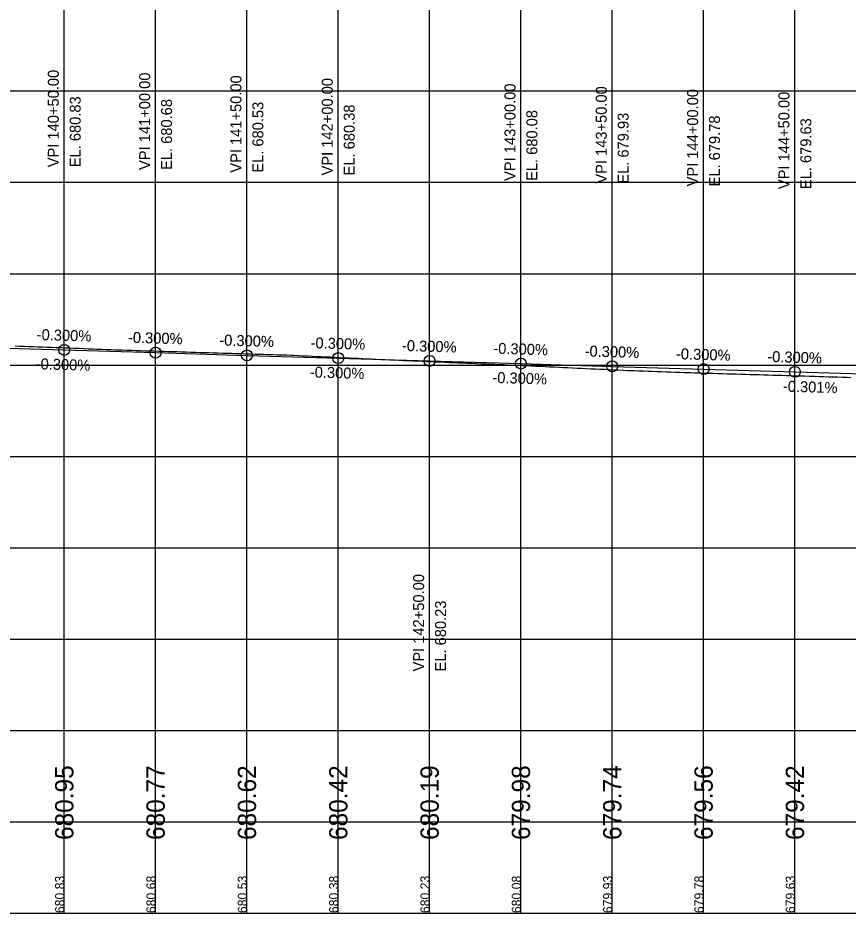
# Model space of a CAD drawing. Extents: x -7164 to 2214450, y -19642 to 253469.
# Drawn here: x 21224.6 to 21679.1, y -3000 to -2510 of the extents above; entities that cross this region are included whole.
import ezdxf

# ---------------------------------------------------------------- set-up
doc = ezdxf.new("R2010")
doc.units = 0
for name, color, linetype in [('DESIGN - PROFILE - Proposed', 7, 'Continuous'), ('DESIGN - PROFILE - Proposed Curve Text', 7, 'Continuous'), ('DESIGN - PROFILE - Proposed Text', 7, 'Continuous'), ('DESIGN - SCRATCH - User 1', 7, 'Continuous'), ('DESIGN - SHEET - Light Grid', 7, 'Continuous'), ('SURVEY - PROFILE - Ground Line with Text', 7, 'Continuous')]:
    doc.layers.add(name, color=color, linetype=linetype)

msp = doc.modelspace()

# ---------------------------------------------------------------- linework, layer by layer
at = {"layer": 'DESIGN - PROFILE - Proposed'}
msp.add_lwpolyline([(21200, -2690.23), (21250, -2691.73), (21300, -2693.23), (21350, -2694.73), (21400, -2696.23), (21450, -2697.73), (21500, -2699.23), (21550, -2700.73), (21600, -2702.23), (21650, -2703.73), (21700, -2705.23)], dxfattribs=at)
msp.add_lwpolyline([(21200, -2690.23), (21250, -2691.73), (21300, -2693.23), (21350, -2694.73), (21400, -2696.23), (21450, -2697.73), (21500, -2699.23), (21550, -2700.73), (21600, -2702.23), (21650, -2703.73), (21700, -2705.23)], dxfattribs=at)
at = {"layer": 'DESIGN - PROFILE - Proposed Text'}
for centre in [(21250, -2691.73), (21250, -2691.73), (21300, -2693.23), (21300, -2693.23), (21350, -2694.73), (21350, -2694.73), (21400, -2696.23), (21400, -2696.23), (21450, -2697.73), (21450, -2697.73), (21500, -2699.23), (21500, -2699.23), (21550, -2700.73), (21550, -2700.73), (21600, -2702.23), (21600, -2702.23), (21650, -2703.73), (21650, -2703.73)]:
    msp.add_circle(centre, 3, dxfattribs=at)
at = {"layer": 'DESIGN - SCRATCH - User 1'}
msp.add_line((15000, -3000), (24100, -3000), dxfattribs=at)
msp.add_line((15000, -3000), (24100, -3000), dxfattribs=at)
at = {"layer": 'DESIGN - SHEET - Light Grid'}
for p, q in [((21250, -3000), (21250, -1000)), ((21250, -3000), (21250, -1000)), ((21300, -3000), (21300, -1000)), ((21300, -3000), (21300, -1000)), ((21350, -3000), (21350, -1000)), ((21350, -3000), (21350, -1000)), ((21400, -3000), (21400, -1000)), ((21400, -3000), (21400, -1000)), ((21450, -3000), (21450, -1000)), ((21450, -3000), (21450, -1000)), ((21500, -3000), (21500, -1000)), ((21500, -3000), (21500, -1000)), ((21550, -3000), (21550, -1000)), ((21550, -3000), (21550, -1000)), ((21600, -3000), (21600, -1000)), ((21600, -3000), (21600, -1000)), ((21650, -3000), (21650, -1000)), ((21650, -3000), (21650, -1000)), ((15000, -2550), (24100, -2550)), ((15000, -2550), (24100, -2550)), ((15000, -2600), (24100, -2600)), ((15000, -2600), (24100, -2600)), ((15000, -2650), (24100, -2650)), ((15000, -2650), (24100, -2650)), ((15000, -2700), (24100, -2700)), ((15000, -2700), (24100, -2700)), ((15000, -2750), (24100, -2750)), ((15000, -2750), (24100, -2750)), ((15000, -2800), (24100, -2800)), ((15000, -2800), (24100, -2800)), ((15000, -2850), (24100, -2850)), ((15000, -2850), (24100, -2850)), ((15000, -2900), (24100, -2900)), ((15000, -2900), (24100, -2900)), ((15000, -2950), (24100, -2950)), ((15000, -2950), (24100, -2950)), ((15000, -3000), (24100, -3000)), ((15000, -3000), (24100, -3000))]:
    msp.add_line(p, q, dxfattribs=at)
at = {"layer": 'SURVEY - PROFILE - Ground Line with Text'}
for points in [[(21223.08, -2689.48), (21225.62, -2689.59), (21228.08, -2689.67), (21230.62, -2689.79), (21233.08, -2689.87), (21235.62, -2689.98), (21238.08, -2690.07), (21240.62, -2690.18), (21243.08, -2690.26), (21245.62, -2690.38), (21248.08, -2690.46), (21250.62, -2690.57), (21253.08, -2690.65), (21255.62, -2690.77), (21258.08, -2690.85), (21260.62, -2690.96), (21263.08, -2691.05), (21265.62, -2691.16), (21268.08, -2691.24), (21270.62, -2691.36), (21273.08, -2691.44), (21275.62, -2691.55), (21278.08, -2691.64), (21279.23, -2691.67), (21281.77, -2691.75), (21284.23, -2691.83), (21286.77, -2691.91), (21289.23, -2691.99), (21291.77, -2692.06), (21294.23, -2692.15), (21296.77, -2692.22), (21299.23, -2692.31), (21299.25, -2692.31), (21301.79, -2692.38), (21304.25, -2692.46), (21306.79, -2692.54), (21309.25, -2692.61), (21311.79, -2692.69), (21314.25, -2692.76), (21316.79, -2692.84), (21319.25, -2692.91), (21321.79, -2692.99), (21324.25, -2693.07), (21326.79, -2693.14), (21329.25, -2693.22), (21331.79, -2693.29), (21334.25, -2693.37), (21336.79, -2693.45), (21339.25, -2693.52), (21341.79, -2693.6), (21344.25, -2693.67), (21346.78, -2693.75), (21349.25, -2693.82), (21351.78, -2693.9), (21354.25, -2693.98), (21356.78, -2694.05), (21359.25, -2694.13), (21361.78, -2694.2), (21364.25, -2694.28), (21366.78, -2694.36), (21369.25, -2694.43), (21371.78, -2694.51), (21374.25, -2694.58), (21374.77, -2694.61), (21375.72, -2694.65), (21378.2, -2694.78), (21380.72, -2694.89), (21383.2, -2695.02), (21385.72, -2695.13), (21388.2, -2695.26), (21390.72, -2695.37), (21393.2, -2695.5), (21395.72, -2695.61), (21398.2, -2695.74), (21400.72, -2695.85), (21403.2, -2695.98), (21405.72, -2696.09), (21408.2, -2696.22), (21410.72, -2696.33), (21413.2, -2696.46), (21415.72, -2696.56), (21415.77, -2696.57), (21418.25, -2696.68), (21420.77, -2696.79), (21423.24, -2696.9), (21425.77, -2697.01), (21428.24, -2697.13), (21430.77, -2697.23), (21433.24, -2697.35), (21435.77, -2697.45), (21438.24, -2697.57), (21440.77, -2697.68), (21443.24, -2697.79)], [(21223.08, -2689.48), (21225.62, -2689.59), (21228.08, -2689.67), (21230.62, -2689.79), (21233.08, -2689.87), (21235.62, -2689.98), (21238.08, -2690.07), (21240.62, -2690.18), (21243.08, -2690.26), (21245.62, -2690.38), (21248.08, -2690.46), (21250.62, -2690.57), (21253.08, -2690.65), (21255.62, -2690.77), (21258.08, -2690.85), (21260.62, -2690.96), (21263.08, -2691.05), (21265.62, -2691.16), (21268.08, -2691.24), (21270.62, -2691.36), (21273.08, -2691.44), (21275.62, -2691.55), (21278.08, -2691.64), (21279.23, -2691.67), (21281.77, -2691.75), (21284.23, -2691.83), (21286.77, -2691.91), (21289.23, -2691.99), (21291.77, -2692.06), (21294.23, -2692.15), (21296.77, -2692.22), (21299.23, -2692.31), (21299.25, -2692.31), (21301.79, -2692.38), (21304.25, -2692.46), (21306.79, -2692.54), (21309.25, -2692.61), (21311.79, -2692.69), (21314.25, -2692.76), (21316.79, -2692.84), (21319.25, -2692.91), (21321.79, -2692.99), (21324.25, -2693.07), (21326.79, -2693.14), (21329.25, -2693.22), (21331.79, -2693.29), (21334.25, -2693.37), (21336.79, -2693.45), (21339.25, -2693.52), (21341.79, -2693.6), (21344.25, -2693.67), (21346.78, -2693.75), (21349.25, -2693.82), (21351.78, -2693.9), (21354.25, -2693.98), (21356.78, -2694.05), (21359.25, -2694.13), (21361.78, -2694.2), (21364.25, -2694.28), (21366.78, -2694.36), (21369.25, -2694.43), (21371.78, -2694.51), (21374.25, -2694.58), (21374.77, -2694.61), (21375.72, -2694.65), (21378.2, -2694.78), (21380.72, -2694.89), (21383.2, -2695.02), (21385.72, -2695.13), (21388.2, -2695.26), (21390.72, -2695.37), (21393.2, -2695.5), (21395.72, -2695.61), (21398.2, -2695.74), (21400.72, -2695.85), (21403.2, -2695.98), (21405.72, -2696.09), (21408.2, -2696.22), (21410.72, -2696.33), (21413.2, -2696.46), (21415.72, -2696.56), (21415.77, -2696.57), (21418.25, -2696.68), (21420.77, -2696.79), (21423.24, -2696.9), (21425.77, -2697.01), (21428.24, -2697.13), (21430.77, -2697.23), (21433.24, -2697.35), (21435.77, -2697.45), (21438.24, -2697.57), (21440.77, -2697.68), (21443.24, -2697.79)], [(21443.24, -2697.79), (21445.77, -2697.9), (21448.24, -2698.01), (21450.77, -2698.12), (21453.23, -2698.23), (21455.77, -2698.34), (21458.23, -2698.46), (21460.77, -2698.55), (21463.23, -2698.66), (21465.77, -2698.75), (21468.23, -2698.87), (21470.77, -2698.96), (21473.24, -2699.07), (21475.77, -2699.16), (21478.24, -2699.28), (21480.77, -2699.37), (21483.24, -2699.48), (21485.77, -2699.57), (21488.24, -2699.69), (21490.77, -2699.78), (21493.24, -2699.9), (21495.77, -2699.99), (21496.4, -2700.02), (21498.23, -2700.1), (21500.71, -2700.22), (21503.23, -2700.34), (21505.71, -2700.46), (21508.23, -2700.57), (21510.71, -2700.7), (21513.23, -2700.81), (21515.71, -2700.94), (21518.23, -2701.05), (21520.71, -2701.17), (21523.23, -2701.29), (21525.71, -2701.41), (21528.23, -2701.52), (21530.71, -2701.65), (21533.23, -2701.76), (21535.71, -2701.88), (21538.23, -2702), (21540.71, -2702.12), (21543.23, -2702.23), (21545.71, -2702.36), (21548.23, -2702.47), (21550.71, -2702.6), (21553.23, -2702.71), (21555.71, -2702.83), (21558.23, -2702.95), (21559.45, -2702.98), (21561.92, -2703.05), (21564.45, -2703.16), (21566.92, -2703.23), (21569.45, -2703.35), (21571.92, -2703.42), (21574.45, -2703.53), (21576.92, -2703.6), (21579.45, -2703.71), (21581.92, -2703.78), (21584.45, -2703.9), (21586.92, -2703.97), (21589.45, -2704.08), (21590.43, -2704.11), (21592.9, -2704.18), (21595.43, -2704.25), (21597.9, -2704.32), (21600.43, -2704.4), (21602.9, -2704.47), (21605.43, -2704.54), (21607.9, -2704.61), (21610.43, -2704.69), (21612.9, -2704.76), (21615.43, -2704.83), (21617.91, -2704.9), (21620.43, -2704.98), (21622.91, -2705.05), (21625.43, -2705.12), (21627.91, -2705.19), (21630.43, -2705.26), (21632.91, -2705.33), (21635.43, -2705.41), (21637.91, -2705.48), (21640.43, -2705.55), (21642.91, -2705.62), (21645.43, -2705.7), (21647.91, -2705.77), (21650.43, -2705.84), (21652.91, -2705.91), (21655.42, -2705.99), (21657.91, -2706.06), (21660.42, -2706.13), (21660.89, -2706.14), (21663.38, -2706.23), (21665.89, -2706.3), (21668.38, -2706.38), (21670.89, -2706.46), (21673.38, -2706.54), (21675.89, -2706.61), (21678.38, -2706.7), (21680.89, -2706.77)], [(21443.24, -2697.79), (21445.77, -2697.9), (21448.24, -2698.01), (21450.77, -2698.12), (21453.23, -2698.23), (21455.77, -2698.34), (21458.23, -2698.46), (21460.77, -2698.55), (21463.23, -2698.66), (21465.77, -2698.75), (21468.23, -2698.87), (21470.77, -2698.96), (21473.24, -2699.07), (21475.77, -2699.16), (21478.24, -2699.28), (21480.77, -2699.37), (21483.24, -2699.48), (21485.77, -2699.57), (21488.24, -2699.69), (21490.77, -2699.78), (21493.24, -2699.9), (21495.77, -2699.99), (21496.4, -2700.02), (21498.23, -2700.1), (21500.71, -2700.22), (21503.23, -2700.34), (21505.71, -2700.46), (21508.23, -2700.57), (21510.71, -2700.7), (21513.23, -2700.81), (21515.71, -2700.94), (21518.23, -2701.05), (21520.71, -2701.17), (21523.23, -2701.29), (21525.71, -2701.41), (21528.23, -2701.52), (21530.71, -2701.65), (21533.23, -2701.76), (21535.71, -2701.88), (21538.23, -2702), (21540.71, -2702.12), (21543.23, -2702.23), (21545.71, -2702.36), (21548.23, -2702.47), (21550.71, -2702.6), (21553.23, -2702.71), (21555.71, -2702.83), (21558.23, -2702.95), (21559.45, -2702.98), (21561.92, -2703.05), (21564.45, -2703.16), (21566.92, -2703.23), (21569.45, -2703.35), (21571.92, -2703.42), (21574.45, -2703.53), (21576.92, -2703.6), (21579.45, -2703.71), (21581.92, -2703.78), (21584.45, -2703.9), (21586.92, -2703.97), (21589.45, -2704.08), (21590.43, -2704.11), (21592.9, -2704.18), (21595.43, -2704.25), (21597.9, -2704.32), (21600.43, -2704.4), (21602.9, -2704.47), (21605.43, -2704.54), (21607.9, -2704.61), (21610.43, -2704.69), (21612.9, -2704.76), (21615.43, -2704.83), (21617.91, -2704.9), (21620.43, -2704.98), (21622.91, -2705.05), (21625.43, -2705.12), (21627.91, -2705.19), (21630.43, -2705.26), (21632.91, -2705.33), (21635.43, -2705.41), (21637.91, -2705.48), (21640.43, -2705.55), (21642.91, -2705.62), (21645.43, -2705.7), (21647.91, -2705.77), (21650.43, -2705.84), (21652.91, -2705.91), (21655.42, -2705.99), (21657.91, -2706.06), (21660.42, -2706.13), (21660.89, -2706.14), (21663.38, -2706.23), (21665.89, -2706.3), (21668.38, -2706.38), (21670.89, -2706.46), (21673.38, -2706.54), (21675.89, -2706.61), (21678.38, -2706.7), (21680.89, -2706.77)]]:
    msp.add_lwpolyline(points, dxfattribs=at)

# ---------------------------------------------------------------- texts
at = {"layer": 'DESIGN - PROFILE - Proposed Curve Text'}
for s, p in [('VPI 140+50.00', (21247, -2591.73)), ('VPI 140+50.00', (21247, -2591.73)), ('VPI 141+00.00', (21297, -2593.23)), ('VPI 141+00.00', (21297, -2593.23)), ('VPI 141+50.00', (21347, -2594.73)), ('VPI 141+50.00', (21347, -2594.73)), ('VPI 142+00.00', (21397, -2596.23)), ('VPI 142+00.00', (21397, -2596.23)), ('VPI 143+00.00', (21497, -2599.23)), ('VPI 143+00.00', (21497, -2599.23)), ('VPI 143+50.00', (21547, -2600.73)), ('VPI 143+50.00', (21547, -2600.73)), ('VPI 144+00.00', (21597, -2602.23)), ('VPI 144+00.00', (21597, -2602.23)), ('VPI 144+50.00', (21647, -2603.73)), ('VPI 144+50.00', (21647, -2603.73)), ('EL. 680.83', (21259, -2591.73)), ('EL. 680.83', (21259, -2591.73)), ('EL. 680.68', (21309, -2593.23)), ('EL. 680.68', (21309, -2593.23)), ('EL. 680.53', (21359, -2594.73)), ('EL. 680.53', (21359, -2594.73)), ('EL. 680.38', (21409, -2596.23)), ('EL. 680.38', (21409, -2596.23)), ('EL. 680.08', (21509, -2599.23)), ('EL. 680.08', (21509, -2599.23)), ('EL. 679.93', (21559, -2600.73)), ('EL. 679.93', (21559, -2600.73)), ('EL. 679.78', (21609, -2602.23)), ('EL. 679.78', (21609, -2602.23)), ('EL. 679.63', (21659, -2603.73)), ('EL. 679.63', (21659, -2603.73)), ('VPI 142+50.00', (21447, -2867.73)), ('VPI 142+50.00', (21447, -2867.73)), ('EL. 680.23', (21459, -2867.73)), ('EL. 680.23', (21459, -2867.73))]:
    msp.add_text(s, height=6, rotation=90, dxfattribs=at).set_placement(p)
at = {"layer": 'DESIGN - PROFILE - Proposed Text'}
for s, height, rotation, p in [('-0.300%', 6, 358.2816, (21234.84, -2686.28)), ('-0.300%', 6, 358.2816, (21234.84, -2686.28)), ('-0.300%', 6, 358.2816, (21284.79, -2687.78)), ('-0.300%', 6, 358.2816, (21284.79, -2687.78)), ('-0.300%', 6, 358.2816, (21284.84, -2687.78)), ('-0.300%', 6, 358.2816, (21284.84, -2687.78)), ('-0.300%', 6, 358.2816, (21334.79, -2689.28)), ('-0.300%', 6, 358.2816, (21334.79, -2689.28)), ('-0.300%', 6, 358.2816, (21334.84, -2689.28)), ('-0.300%', 6, 358.2816, (21334.84, -2689.28)), ('-0.300%', 6, 358.2816, (21384.79, -2690.78)), ('-0.300%', 6, 358.2816, (21384.79, -2690.78)), ('-0.300%', 6, 358.2816, (21434.79, -2692.28)), ('-0.300%', 6, 358.2816, (21434.79, -2692.28)), ('-0.300%', 6, 358.2816, (21434.84, -2692.28)), ('-0.300%', 6, 358.2816, (21434.84, -2692.28)), ('-0.300%', 6, 358.2816, (21484.84, -2693.78)), ('-0.300%', 6, 358.2816, (21484.84, -2693.78)), ('-0.300%', 6, 358.2816, (21534.79, -2695.28)), ('-0.300%', 6, 358.2816, (21534.79, -2695.28)), ('-0.300%', 6, 358.2816, (21534.84, -2695.28)), ('-0.300%', 6, 358.2816, (21534.84, -2695.28)), ('-0.300%', 6, 358.2816, (21584.79, -2696.78)), ('-0.300%', 6, 358.2816, (21584.79, -2696.78)), ('-0.300%', 6, 358.2816, (21584.84, -2696.78)), ('-0.300%', 6, 358.2816, (21584.84, -2696.78)), ('-0.300%', 6, 358.2816, (21634.79, -2698.28)), ('-0.300%', 6, 358.2816, (21634.79, -2698.28)), ('-0.300%', 6, 358.2816, (21634.84, -2698.28)), ('-0.300%', 6, 358.2816, (21634.84, -2698.28)), ('-0.300%', 6, 358.2816, (21234.31, -2702.27)), ('-0.300%', 6, 358.2816, (21234.31, -2702.27)), ('-0.300%', 6, 358.2816, (21384.36, -2706.77)), ('-0.300%', 6, 358.2816, (21384.36, -2706.77)), ('-0.300%', 6, 358.2816, (21484.31, -2709.77)), ('-0.300%', 6, 358.2816, (21484.31, -2709.77)), ('-0.301%', 6, 358.2772, (21643.37, -2714.54)), ('-0.301%', 6, 358.2772, (21643.37, -2714.54)), ('680.83', 5, 90, (21250, -3000)), ('680.83', 5, 90, (21250, -3000)), ('680.68', 5, 90, (21300, -3000)), ('680.68', 5, 90, (21300, -3000)), ('680.53', 5, 90, (21350, -3000)), ('680.53', 5, 90, (21350, -3000)), ('680.38', 5, 90, (21400, -3000)), ('680.38', 5, 90, (21400, -3000)), ('680.23', 5, 90, (21450, -3000)), ('680.23', 5, 90, (21450, -3000)), ('680.08', 5, 90, (21500, -3000)), ('680.08', 5, 90, (21500, -3000)), ('679.93', 5, 90, (21550, -3000)), ('679.93', 5, 90, (21550, -3000)), ('679.78', 5, 90, (21600, -3000)), ('679.78', 5, 90, (21600, -3000)), ('679.63', 5, 90, (21650, -3000)), ('679.63', 5, 90, (21650, -3000))]:
    msp.add_text(s, height=height, rotation=rotation, dxfattribs=at).set_placement(p)
at = {"layer": 'SURVEY - PROFILE - Ground Line with Text'}
for s, p in [('680.95', (21255, -2960)), ('680.95', (21255, -2960)), ('680.77', (21305, -2960)), ('680.77', (21305, -2960)), ('680.62', (21355, -2960)), ('680.62', (21355, -2960)), ('680.42', (21405, -2960)), ('680.42', (21405, -2960)), ('680.19', (21455, -2960)), ('680.19', (21455, -2960)), ('679.98', (21505, -2960)), ('679.98', (21505, -2960)), ('679.74', (21555, -2960)), ('679.74', (21555, -2960)), ('679.56', (21605, -2960)), ('679.56', (21605, -2960)), ('679.42', (21655, -2960)), ('679.42', (21655, -2960))]:
    msp.add_text(s, height=10, rotation=90, dxfattribs=at).set_placement(p)

doc.saveas('drawing.dxf')
